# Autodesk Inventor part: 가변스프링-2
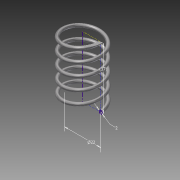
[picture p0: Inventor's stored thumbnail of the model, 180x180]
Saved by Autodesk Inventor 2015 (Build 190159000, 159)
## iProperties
Created: 2016-01
Part Number: 가변스프링-2
Material: 스테인레스 스틸
Document SubType Name: Modeling
Designer: 601-23
Density: 8 g/cm^3
Appearance: 반연마
Mass: 8.58406 g
Surface Area: 21.7283 cm^2
Volume: 1.07301 cm^3
Author: 601-23
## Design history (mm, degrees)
sketch "스케치1"
  geometry: L1 (0, 0)-(11, 0); L2 (11, 0)-(11, 36.411); L3 (11, 36.411)-(0, 36.411); L4 (0, 36.411)-(0, 0); C1 r 1 at (11, 0)
  constraints: 8 end point, 2 parallel, 1 centre point, 1 coincident, 1 horizontal, 1 perpendicular
  dimensions: "d0" = 36.4112 distance of L1.end L2.end (derived); "d1" = 22 diameter of L2 L4; "d2" = 2 diameter of C1
feature "코일1" sketch "스케치1" pitch "d3" = 5; turns "d5" = 5; dims "d4" = 36.4112 (= d0), "d6" = 0, angle "d7" = 90 deg, angle "d8" = 90 deg, "d9" = 0, "d10" = 0
node "작업 평면1"
node "작업 평면2"
sketch "스케치2"
  geometry: L1 (1, 0)-(-1, 0) reference; 1 further point
  constraints: 1 horizontal alignment
extrude "돌출1" cut sketch "스케치2" stored distance "d13" = 10; taper "d14" = 0 deg
sketch "스케치3"
  geometry: L1 (10, 0)-(12, 0) reference; 1 further point
  constraints: 1 horizontal alignment
extrude "돌출2" cut sketch "스케치3" stored distance "d15" = 10; taper "d16" = 0 deg
node "솔리드1"
node "절단 모서리 투영1"
node "절단 모서리 투영2"
other parameters: "d11" = 90 deg, "d12" = 90 deg
